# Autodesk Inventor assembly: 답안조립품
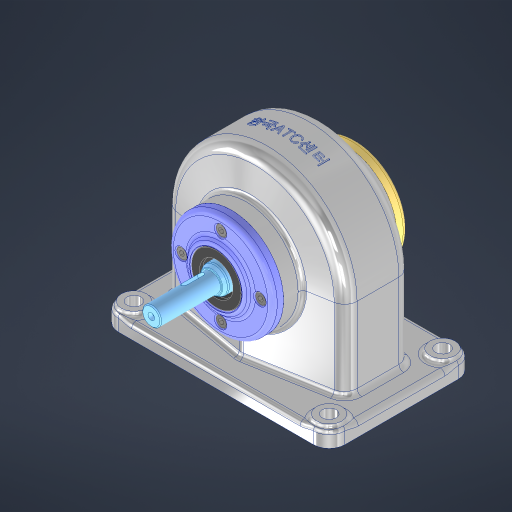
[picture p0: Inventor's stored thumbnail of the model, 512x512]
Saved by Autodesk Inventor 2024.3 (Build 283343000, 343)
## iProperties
Created: 2025-05
Part Number: 답안조립품
Document SubType Name: Assembly
Designer: user
Author: user
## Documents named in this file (13)
- C:\Users\user\Desktop\750503V1001\답안조립품.iam
- C:\Users\user\Desktop\750503V1001\본체.ipt
- C:\Users\user\Desktop\750503V1001\깊은 홈 볼 베어링 6203\깊은 홈 볼 베어링 6203\깊은 홈 볼 베어링 6203.ipt
- C:\Users\user\Desktop\750503V1001\칼라\칼라\칼라.ipt
- C:\Users\user\Desktop\750503V1001\축\축\축.ipt
- C:\Users\user\Desktop\750503V1001\뒷커버\뒷커버\뒷커버.ipt
- C:\Users\user\Desktop\750503V1001\베어링 너트용 와셔 AW03X\베어링 너트용 와셔 AW03X\베어링 너트용 와셔 AW03X.ipt
- C:\Users\user\Desktop\750503V1001\베어링 너트 AN03\베어링 너트 AN03\베어링 너트 AN03.ipt
- C:\Users\user\Desktop\750503V1001\앞커버\앞커버\앞커버.ipt
- C:\Users\user\Desktop\750503V1001\오일 실 17 32 8\오일 실 17 32 8\오일 실 17 32 8.ipt
- C:\Users\user\Desktop\750503V1001\스퍼기어\스퍼기어\스퍼기어.ipt
- C:\Users\user\Desktop\750503V1001\평행 키 5x5x18\평행 키 5x5x18\평행 키 5x5x18.ipt
- C:\Users\user\Desktop\750503V1001\6각 구멍붙이 볼트 M4x8\6각 구멍붙이 볼트 M4x8\6각 구멍붙이 볼트 M4x8.ipt
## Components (8 placed, 1 different names)
1. 6각 구멍붙이 볼트 M4x8:1
2. 6각 구멍붙이 볼트 M4x8:2
3. 6각 구멍붙이 볼트 M4x8:3
4. 6각 구멍붙이 볼트 M4x8:4
5. 6각 구멍붙이 볼트 M4x8:5
6. 6각 구멍붙이 볼트 M4x8:6
7. 6각 구멍붙이 볼트 M4x8:7
8. 6각 구멍붙이 볼트 M4x8:8
